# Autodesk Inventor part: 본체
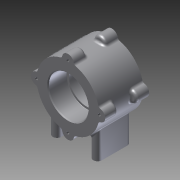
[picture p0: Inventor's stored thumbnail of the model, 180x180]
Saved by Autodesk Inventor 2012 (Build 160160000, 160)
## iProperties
Created: 2015-03
Part Number: 본체
Material: Default
Document SubType Name: Modeling
Designer: narae
Density: 1 g/cm^3
Author: narae
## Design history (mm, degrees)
sketch "스케치1"
  geometry: C1 r 37 at (0, 0); 1 further point
  constraints: 1 centre point, 1 coincident
  dimensions: "d0" = 74 diameter of C1
extrude "돌출1" new body sketch "스케치1" stored distance "d1" = 52; taper "d2" = 0 deg
sketch "스케치2"
  geometry: C1 r 7 at (0, 37); 1 further point
  constraints: 2 vertical alignment, 1 centre point, 1 other
  dimensions: "d3" = 14 diameter of C1
extrude "돌출2" join sketch "스케치2" distance "d4" = 15; taper "d5" = 0 deg
hole "구멍1" diameter "d8" = 3.242; stored, may be unused: countersink angle "d12" = 90 deg, drill point angle "d14" = 118 deg; dims "d6" = 10, "d7" = 10, "d9" = 8, "d10" = 4, "d11" = 2, "d13" = 11
hole "구멍2" diameter "d17" = 47; stored, may be unused: countersink angle "d21" = 90 deg, drill point angle "d23" = 0 deg; dims "d15" = 10, "d16" = 10, "d18" = 8, "d19" = 4, "d20" = 2, "d22" = 22
hole "구멍3" diameter "d26" = 47; stored, may be unused: countersink angle "d30" = 90 deg, drill point angle "d32" = 0 deg; dims "d24" = 10, "d25" = 10, "d27" = 8, "d28" = 4, "d29" = 2, "d31" = 22
hole "구멍4" diameter "d35" = 42; stored, may be unused: countersink angle "d39" = 90 deg, drill point angle "d41" = 0 deg; dims "d33" = 10, "d34" = 10, "d36" = 8, "d37" = 4, "d38" = 2, "d40" = 22
fillet "모깎기1" dims "d42" = 3, "d97" = 0.3
node "작업 평면1"
sketch "스케치3"
  geometry: L1 (-61.6, 0)-(61.6, 0) reference; L2 (0, 36.4)-(0, -36.4) reference; L3 (-29, -15)-(-29, 15); L4 (-19, -15)-(-19, 15); L5 (19, -15)-(19, 15); L6 (29, -15)-(29, 15); A1 r 5 centre (24, -15) between (19, -15) and (29, -15); A2 r 5 centre (24, 15) between (29, 15) and (19, 15); A3 r 5 centre (-24, -15) between (-29, -15) and (-19, -15); A4 r 5 centre (-24, 15) between (-19, 15) and (-29, 15); 1 further point
  constraints: 8 end point, 8 point on circle, 7 tangent, 4 centre point, 3 equal radius, 2 horizontal alignment, 2 symmetric about line, 2 vertical alignment, 1 parallel
  dimensions: "d47" = 10 diameter of A1; "d48" = 40 dimension on A2 A1; "d49" = 48 distance of A1.centre A3.centre
extrude "돌출3" join sketch "스케치3" stored distance "d50" = 15; taper "d51" = 0 deg
hole "구멍5" diameter "d54" = 4.134; stored, may be unused: countersink angle "d58" = 90 deg, drill point angle "d60" = 118 deg; dims "d52" = 10, "d53" = 10, "d55" = 6, "d56" = 4, "d57" = 2, "d59" = 8
hole "구멍7" diameter "d72" = 4.134; stored, may be unused: countersink angle "d76" = 90 deg, drill point angle "d78" = 118 deg; dims "d70" = 10, "d71" = 10, "d73" = 6, "d74" = 4, "d75" = 2, "d77" = 8
hole "구멍8" diameter "d81" = 4.134; stored, may be unused: countersink angle "d85" = 90 deg, drill point angle "d87" = 118 deg; dims "d79" = 10, "d80" = 10, "d82" = 6, "d83" = 4, "d84" = 2, "d86" = 8
hole "구멍9" diameter "d90" = 4.134; stored, may be unused: countersink angle "d94" = 90 deg, drill point angle "d96" = 118 deg; dims "d88" = 10, "d89" = 10, "d91" = 6, "d92" = 4, "d93" = 2, "d95" = 8
chamfer "모따기1" distance "d98" = 1; stored, may be unused: second distance "d99" = 2, angle "d100" = 45 deg
sketch "스케치5"
  geometry: L1 (0, 26)-(0, -26); L2 (24.5, 26)-(-24.5, 26) reference; 3 further points
  constraints: 3 coincident, 2 end point, 2 midpoint, 1 vertical
node "작업 평면7"
  node "작업 평면6"
sketch "스케치7"
  geometry: L1 (-26, -18.921)-(-26, 18.921) reference; 2 further points
  constraints: 1 coincident, 1 other
  dimensions: "d107" = 26 distance from line of L1 point (0, 0)
feature "엠보싱2" sketch "스케치7" dims "d108" = 0.5, "d109" = 0
fillet "모깎기2" dims "d110" = 3
node "솔리드1"
pattern_circular "원형 패턴1" dims "d44" = 360 deg
mirror "대칭1"
other parameters: "d46" = -56, "d106" = 45 deg
